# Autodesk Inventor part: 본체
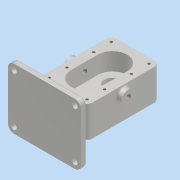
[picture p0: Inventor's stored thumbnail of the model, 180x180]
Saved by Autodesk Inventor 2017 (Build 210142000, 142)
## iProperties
Part Number: 본체
Material: 알루미늄 6061
Document SubType Name: Modeling
Designer: MRC
Density: 2.7 g/cm^3
Appearance: 알루미늄 - 평지
Mass: 1471.81 g
Surface Area: 818.636 cm^2
Volume: 545.115 cm^3
Author: MRC
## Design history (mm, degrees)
sketch "스케치1"
  geometry: L1 (40, -60)-(-40, -60); L2 (-40, -60)-(-40, 60); L3 (-40, 60)-(40, 60); L4 (40, 60)-(40, -60); L5 (40, -60)-(-40, 60); L6 (-40, -60)-(40, 60); 2 further points
  constraints: 12 end point, 3 midpoint, 2 parallel, 1 horizontal, 1 perpendicular
  dimensions: "d0" = 80 distance of L2.end L3.end; "d1" = 120 distance of L1.end L2.end
extrude "돌출1" new body sketch "스케치1" distance "d5" = 14; taper "d7" = 0 deg; dims "d6" = 39, "d8" = 0
sketch "스케치2"
  geometry: L1 (0, -46)-(0, -46); L2 (-24, -22)-(-24, 22); L3 (0, 46)-(0, 46); L4 (24, 22)-(24, -22); L5 (24, -46)-(-24, 46); L6 (-24, -46)-(24, 46); A1 r 24 centre (0, 22) between (0, 46) and (-24, 22); A2 r 24 centre (0, 22) between (24, 22) and (0, 46); A3 r 24 centre (0, -22) between (-24, -22) and (0, -46); A4 r 24 centre (0, -22) between (0, -46) and (24, -22); 1 further point
  constraints: 12 end point, 8 point on circle, 8 point on line, 8 tangent, 4 centre point, 3 equal radius, 2 midpoint, 2 parallel, 1 horizontal, 1 perpendicular
  dimensions: "d9" = 48 distance of L5.end L6.end; "d10" = 92 distance of L6.start L5.end; "d11" = 24 radius of A1
extrude "돌출2" cut sketch "스케치2" distance "d12" = 29; taper "d13" = 0 deg
sketch "스케치3"
  geometry: C1 r 11 at (14, 60); 1 further point
  constraints: 1 centre point, 1 coincident
  dimensions: "d14" = 22 diameter of C1
extrude "돌출3" join sketch "스케치3" distance "d15" = 8; taper "d16" = 0 deg
sketch "스케치4"
  geometry: C1 r 11 at (0, 0) reference; 1 further point
  constraints: 1 coincident
hole "구멍1" sketch "스케치4" at (0, 0) diameter "d17" = 8.376; stored, may be unused: countersink angle "d21" = 90 deg, drill point angle "d23" = 118 deg; dims "d18" = 96, "d19" = 4, "d20" = 2, "d22" = 27.3
sketch "스케치5"
  geometry: C1 r 4.188 at (-14, 60) reference; C2 r 11 at (-14, 60)
  constraints: 1 centre point, 1 coincident
  dimensions: "d24" = 22 diameter of C2
extrude "돌출4" join sketch "스케치5" distance "d25" = 8; taper "d26" = 0 deg
sketch "스케치6"
  geometry: C1 r 12.5 at (0, 22); C2 r 12.5 at (0, -22); A1 r 24 centre (0, -22) between (-24, -22) and (24, -22) reference; A2 r 24 centre (0, 22) between (24, 22) and (-24, 22) reference; 1 further point
  constraints: 2 centre point, 2 coincident
  dimensions: "d27" = 25 diameter of C1; "d28" = 25 diameter of C2
extrude "돌출5" cut sketch "스케치6" distance "d29" = 15; taper "d30" = 0 deg
sketch "스케치7"
  geometry: C1 r 12.5 at (0, 0) reference; C2 r 8.5 at (0, 0); 1 further point
  constraints: 1 centre point, 1 coincident
  dimensions: "d31" = 17 diameter of C2
extrude "돌출6" cut sketch "스케치7" stored distance "d32" = 15; taper "d33" = 0 deg
sketch "스케치8"
  geometry: C1 r 8.5 at (0, 22) reference; C2 r 19 at (0, 22); 1 further point
  constraints: 1 centre point, 1 coincident
  dimensions: "d34" = 38 diameter of C2
extrude "돌출7" join sketch "스케치8" distance "d35" = 17; taper "d36" = 0 deg
sketch "스케치9"
  geometry: L1 (3, -56)-(41, -56) reference; L2 (22, -56)-(22, -30); L3 (13.5, -30)-(30.5, -30) reference; L4 (36.404, -56)-(36, -55.3); L5 (36, -55.3)-(22, -55.3); L6 (22, -56)-(36.404, -56); L7 (36, -55.3)-(36, -48); L8 (36, -48)-(22, -48); 1 further point
  constraints: 12 end point, 3 point on line, 2 midpoint, 2 perpendicular, 1 parallel, 1 vertical
  dimensions: "d37" = 28 diameter of L7 L2; "d38" = 30 deg angle of L4 L7; "d39" = 0.7 distance between parallel lines of L1 L5; "d40" = 7.3 distance between parallel lines of L5 L8
revolve "회전1" sketch "스케치9" stored, may be unused: angle "d41" = 90 deg
sketch "스케치10"
  geometry: L1 (-60, -112)-(60, -112); L2 (60, -112)-(60, -102); L3 (60, -102)-(-60, -102); L4 (-60, -102)-(-60, -112); L5 (40, 38)-(-40, 38) reference; 2 further points
  constraints: 8 end point, 2 parallel, 1 horizontal, 1 midpoint, 1 perpendicular, 1 vertical alignment
  dimensions: "d43" = 10 distance of L3.end L1.start; "d44" = 120 distance of L1.start L1.end; "d84" = 150 distance between parallel lines of L1 L5
extrude "돌출8" join sketch "스케치10" distance "d45" = 100; taper "d46" = 0 deg
fillet "모깎기1" dims "d47" = 9
sketch "스케치11"
  geometry: A1 r 9 centre (31, 51) between (40, 51) and (31, 60) reference; A2 r 9 centre (-31, 51) between (-31, 60) and (-40, 51) reference; A3 r 9 centre (-31, -51) between (-40, -51) and (-31, -60) reference; A4 r 9 centre (31, -51) between (31, -60) and (40, -51) reference; 9 further points
  constraints: 4 coincident, 4 vertical alignment
  dimensions: "d55" = 29 distance of point (31, 51) point (31, 22); "d56" = 44 distance of point (31, 22) point (31, -22); "d57" = 44 distance of point (-31, -22) point (-31, 22); "d58" = 29 distance of point (-31, 51) point (-31, 22)
hole "구멍2" sketch "스케치11" at (-31, 51), (31, 51), (31, -51), (-31, -51), (31, -22), (31, 22), (-31, -22), (-31, 22) diameter "d48" = 4.134; stored, may be unused: countersink angle "d52" = 90 deg, drill point angle "d54" = 118 deg; dims "d49" = 10, "d50" = 4, "d51" = 2, "d53" = 12
sketch "스케치12"
  geometry: L1 (-80, -39)-(-60, -27.453); L2 (-80, 14)-(-60, 2.453); L3 (-90, -56)-(-80, -56) reference; L4 (-80, -56)-(-80, 44) reference; L5 (-60, -39)-(-60, 14) reference; L6 (-60, 2.453)-(-60, -27.453); 1 further point
  constraints: 6 end point, 4 point on line, 1 collinear
  dimensions: "d60" = 17 distance from line of L3 L1.start; "d61" = 53 distance of L2.start L1.start; "d62" = 60 deg angle of L4 L1; "d63" = 60 deg angle of L4 L2
extrude "돌출9" join sketch "스케치12" stored distance "d64" = 48; taper "d65" = 0 deg
fillet "모깎기2" dims "d66" = 10
fillet "모깎기3" dims "d67" = 3, "d68" = 0.5
sketch "스케치13"
  geometry: C1 r 4.5 at (100, 7); C2 r 4.5 at (0, 7); C3 r 4.5 at (0, 87); C4 r 4.5 at (100, 87); A1 r 7 centre (0, 7) between (-7, 7) and (0, 0) reference; A2 r 7 centre (100, 7) between (100, 0) and (107, 7) reference; A3 r 7 centre (100, 87) between (107, 87) and (100, 94) reference; A4 r 7 centre (0, 87) between (0, 94) and (-7, 87) reference; 1 further point
  constraints: 4 centre point, 4 coincident
  dimensions: "d69" = 9 diameter of C1; "d70" = 9 diameter of C2; "d71" = 9 diameter of C3; "d72" = 9 diameter of C4
extrude "돌출10" cut sketch "스케치13" distance "d73" = 48; taper "d74" = 0 deg
fillet "모깎기4" dims "d75" = 3
chamfer "모따기1" distance "d76" = 1; stored, may be unused: second distance "d77" = 2, angle "d78" = 45 deg
sketch "스케치14"
  geometry: L1 (0, -3)-(100, -3) reference; L2 (-10, 87)-(-10, 7) reference; 2 further points
  constraints: 1 other
  dimensions: "d79" = 10 distance from line of L1 point (50, 7); "d80" = 60 distance from line of point (50, 7) L2
feature "엠보싱1" sketch "스케치14" dims "d0" = 80, "d1" = 120, "d9" = 48, "d10" = 92, "d11" = 24, "d81" = 0.5, "d82" = 0
fillet "모깎기5" dims "d83" = 3
node "솔리드1"
